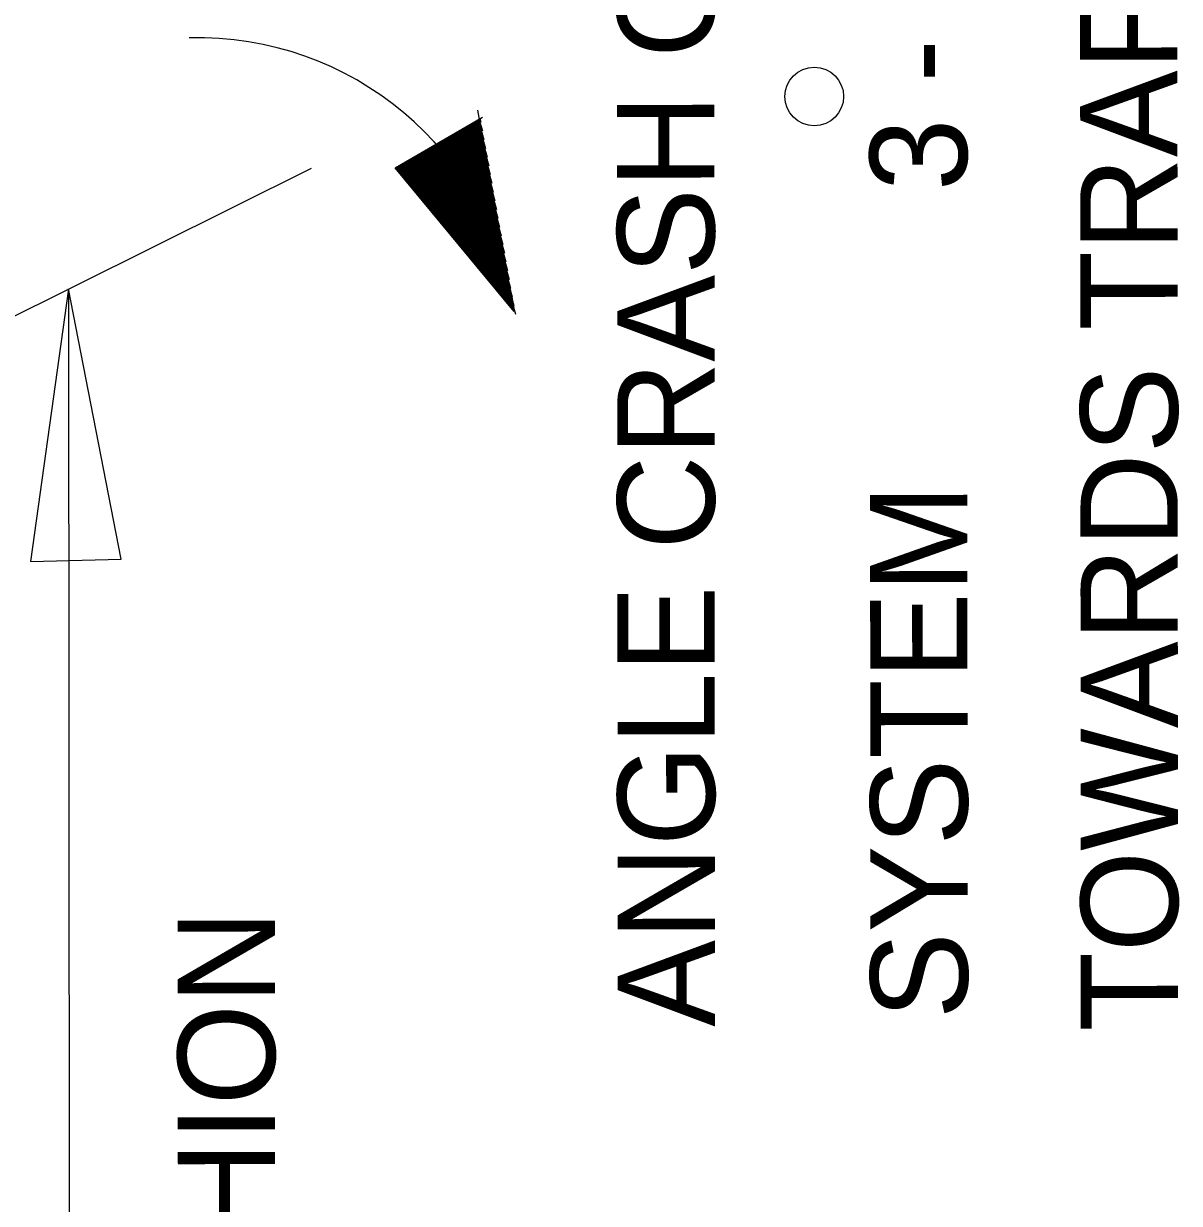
# Model space of a CAD drawing. Extents: x 612.5 to 619.9, y 611 to 621.1.
# Drawn here: x 616.652 to 617.365, y 619.273 to 620.001 of the extents above; entities that cross this region are included whole.
import ezdxf

# ---------------------------------------------------------------- set-up
doc = ezdxf.new("R2010")
doc.units = 0
doc.layers.add('DETL-DIMS', color=7, linetype='Continuous')
doc.layers.add('DETL-NOTE', color=7, linetype='Continuous')

msp = doc.modelspace()

# ---------------------------------------------------------------- linework, layer by layer
at = {"layer": 'DETL-DIMS'}
for p, q in [((616.93224, 619.9474), (616.95436, 619.8238)), ((616.88144, 619.91172), (616.9352, 619.943)), ((616.92732, 619.93844), (616.9468, 619.86988)), ((616.9278, 619.93876), (616.94584, 619.87524)), ((616.92824, 619.93904), (616.9448, 619.88068)), ((616.9288, 619.93928), (616.94392, 619.88604)), ((616.92924, 619.93964), (616.94292, 619.89144)), ((616.92976, 619.93984), (616.94196, 619.89684)), ((616.93028, 619.94016), (616.94108, 619.9022)), ((616.93072, 619.94052), (616.94008, 619.9076)), ((616.9312, 619.94072), (616.93912, 619.91296)), ((616.93168, 619.94104), (616.93808, 619.9184)), ((616.93216, 619.94124), (616.93712, 619.92372)), ((616.93268, 619.9416), (616.9362, 619.92916)), ((616.93312, 619.94188), (616.93524, 619.93452)), ((616.93364, 619.94212), (616.93424, 619.93996)), ((616.91524, 619.93128), (616.9414, 619.83936)), ((616.91568, 619.9316), (616.94224, 619.83832)), ((616.91612, 619.93192), (616.94312, 619.8372)), ((616.9166, 619.93212), (616.94392, 619.8362)), ((616.91716, 619.93244), (616.94488, 619.83516)), ((616.9176, 619.93272), (616.94572, 619.83416)), ((616.91812, 619.933), (616.94656, 619.83312)), ((616.91864, 619.93332), (616.94748, 619.83204)), ((616.91912, 619.93356), (616.94832, 619.831)), ((616.91956, 619.93388), (616.94916, 619.82996)), ((616.92004, 619.93412), (616.95, 619.82892)), ((616.92048, 619.9344), (616.9508, 619.82792)), ((616.921, 619.93476), (616.95176, 619.82688)), ((616.92148, 619.93504), (616.9526, 619.82584)), ((616.92196, 619.93536), (616.95344, 619.82484)), ((616.92252, 619.93564), (616.95436, 619.8238)), ((616.92296, 619.93592), (616.95556, 619.82144)), ((616.92344, 619.93624), (616.9546, 619.82676)), ((616.92388, 619.93648), (616.9536, 619.83212)), ((616.92436, 619.9368), (616.9526, 619.83756)), ((616.92492, 619.93704), (616.95176, 619.84292)), ((616.92536, 619.93732), (616.95076, 619.84836)), ((616.92584, 619.93768), (616.94976, 619.85368)), ((616.9264, 619.93792), (616.94876, 619.85912)), ((616.92684, 619.9382), (616.9478, 619.86448)), ((616.90252, 619.92396), (616.91884, 619.8664)), ((616.90308, 619.92428), (616.9198, 619.86544)), ((616.90356, 619.92452), (616.92064, 619.86428)), ((616.904, 619.92484), (616.92148, 619.86324)), ((616.90448, 619.92508), (616.92232, 619.86224)), ((616.90492, 619.92536), (616.92316, 619.8612)), ((616.90548, 619.9256), (616.92404, 619.8602)), ((616.90592, 619.92592), (616.92492, 619.85908)), ((616.9064, 619.92624), (616.92576, 619.85804)), ((616.907, 619.92648), (616.92672, 619.85704)), ((616.90744, 619.92684), (616.92752, 619.856)), ((616.90792, 619.92704), (616.92836, 619.85496)), ((616.90836, 619.92732), (616.9292, 619.85396)), ((616.9088, 619.92768), (616.93012, 619.85284)), ((616.90936, 619.92792), (616.93108, 619.85184)), ((616.90984, 619.9282), (616.93192, 619.8508)), ((616.91028, 619.92844), (616.93276, 619.84976)), ((616.91088, 619.9288), (616.93368, 619.84876)), ((616.91132, 619.92908), (616.93452, 619.84764)), ((616.9118, 619.92932), (616.93536, 619.8466)), ((616.91224, 619.92964), (616.9362, 619.8456)), ((616.91272, 619.92988), (616.93704, 619.84452)), ((616.91324, 619.93016), (616.93796, 619.84356)), ((616.91372, 619.93048), (616.93884, 619.84244)), ((616.91416, 619.93072), (616.93964, 619.8414)), ((616.91476, 619.93108), (616.94056, 619.8404)), ((616.89036, 619.91692), (616.89732, 619.89248)), ((616.89084, 619.9172), (616.89816, 619.89136)), ((616.8914, 619.91744), (616.89912, 619.89036)), ((616.89188, 619.91776), (616.89996, 619.88932)), ((616.89236, 619.918), (616.90076, 619.88828)), ((616.8928, 619.91832), (616.9016, 619.88724)), ((616.89324, 619.9186), (616.90248, 619.88616)), ((616.8938, 619.91888), (616.9034, 619.88512)), ((616.89424, 619.91916), (616.9042, 619.88412)), ((616.89472, 619.9194), (616.90504, 619.88308)), ((616.89532, 619.91972), (616.906, 619.88208)), ((616.89576, 619.92004), (616.90684, 619.88096)), ((616.89624, 619.92028), (616.90768, 619.87992)), ((616.89668, 619.92056), (616.90852, 619.87888)), ((616.89716, 619.92084), (616.90936, 619.87784)), ((616.89768, 619.92116), (616.91028, 619.87684)), ((616.89816, 619.92144), (616.91112, 619.8758)), ((616.89864, 619.92164), (616.91196, 619.87472)), ((616.8992, 619.92204), (616.91292, 619.87368)), ((616.89968, 619.92224), (616.91376, 619.87264)), ((616.90012, 619.92256), (616.91456, 619.87164)), ((616.90056, 619.92288), (616.9154, 619.8706)), ((616.90104, 619.92308), (616.91628, 619.86948)), ((616.90156, 619.9234), (616.91716, 619.86848)), ((616.90204, 619.92364), (616.918, 619.86744)), ((616.35384, 619.6746), (616.82976, 619.91164)), ((616.95492, 619.82308), (616.88144, 619.91172)), ((616.8816, 619.91176), (616.88176, 619.91116)), ((616.88212, 619.91212), (616.88268, 619.9102)), ((616.8826, 619.91232), (616.88352, 619.90912)), ((616.88304, 619.91264), (616.88436, 619.908)), ((616.88364, 619.913), (616.88532, 619.90704)), ((616.88408, 619.9132), (616.88616, 619.90596)), ((616.88456, 619.91352), (616.887, 619.90496)), ((616.88504, 619.91372), (616.8878, 619.90392)), ((616.88548, 619.91408), (616.88864, 619.90292)), ((616.886, 619.91436), (616.8896, 619.9018)), ((616.88648, 619.9146), (616.89044, 619.90076)), ((616.88692, 619.91492), (616.89124, 619.89972)), ((616.88752, 619.9152), (616.8922, 619.89872)), ((616.888, 619.91548), (616.89304, 619.89772)), ((616.88844, 619.91576), (616.89388, 619.89656)), ((616.88892, 619.91604), (616.89472, 619.89556)), ((616.88936, 619.91632), (616.89556, 619.89452)), ((616.88992, 619.91656), (616.89648, 619.89352)), ((616.68008, 619.83708), (616.68156, 617.77704))]:
    msp.add_line(p, q, dxfattribs=at)
msp.add_lwpolyline([(616.65664, 619.66888), (616.71244, 619.67036), (616.68008, 619.83708)], close=True, dxfattribs=at)
msp.add_arc((616.75964, 619.79434), 0.19764, 8.64674, 91.49751, dxfattribs=at)
at = {"layer": 'DETL-NOTE'}
msp.add_circle((617.13989, 619.95573), 0.01809, dxfattribs=at)

# ---------------------------------------------------------------- texts
for s, p in [('ANGLE CRASH CUSHION', (617.07868, 619.382)), ('TOWARDS TRAFFIC.', (617.36424, 619.37908)), ('3 - 10', (617.23412, 619.89748)), ('SYSTEM', (617.23452, 619.38676)), ('CENTER OF FIRST CUSHION', (616.80808, 618.34408))]:
    msp.add_text(s, height=0.06, rotation=90.03987, dxfattribs=at).set_placement(p)

doc.saveas('drawing.dxf')
